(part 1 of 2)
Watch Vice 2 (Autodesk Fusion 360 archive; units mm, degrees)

design "Watch Vice 2" references "WatchCase V3"
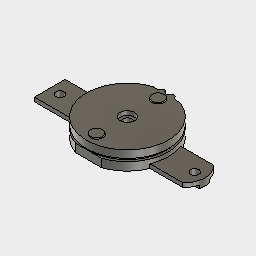
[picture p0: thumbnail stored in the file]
parameter "d90" = 4
parameter "d106" = 4
component_insert "Component Insert"
sketch "Sketch1"
  line L1 (0, 20.2285) -> (0, 20.1)
  line L2 (0, 20.95) -> (0, 20.2285)
  arc A1 centre (0, 0) radius 20.1 clockwise from (19.4682, -5) to (-3.612, 19.7728)
  arc A2 centre (19.1697, -3.3264) radius 1.7 clockwise from (20.869, -3.3751) to (19.4682, -5)
  arc A3 centre (-96.8326, 0) radius 117.75 clockwise from (20.869, 3.3751) to (20.869, -3.3751)
  arc A4 centre (19.1697, 3.3264) radius 1.7 clockwise from (19.4682, 5) to (20.869, 3.3751)
  arc A5 centre (0, 0) radius 20.1 clockwise from (3.612, 19.7728) to (19.4682, 5)
  arc A6 centre (2.1023, 18.9913) radius 1.7 clockwise from (0.8, 20.0841) to (3.612, 19.7728)
  arc A7 centre (0, 0) radius 20.1 clockwise from (-0.8, 20.0841) to (0.8, 20.0841)
  arc A8 centre (-2.1023, 18.9913) radius 1.7 clockwise from (-3.612, 19.7728) to (-0.8, 20.0841)
  arc A9 centre (0, 0) radius 21.6 clockwise from (-17.2241, -13.0342) to (-17.2241, 13.0342)
  arc A10 centre (-18.5, 13.9997) radius 1.6 clockwise from (-16.9962, 14.5462) to (-17.2241, 13.0342)
  arc A11 centre (-15.2104, 15.1952) radius 1.9 clockwise from (-16.9962, 14.5462) to (-14.5633, 16.9815)
  arc A12 centre (-14.0183, 18.4859) radius 1.6 clockwise from (-13.0515, 17.211) to (-14.5633, 16.9815)
  arc A13 centre (0, 0) radius 21.6 clockwise from (-13.0515, 17.211) to (13.0515, 17.211)
  arc A14 centre (14.0183, 18.4859) radius 1.6 clockwise from (14.5633, 16.9815) to (13.0515, 17.211)
  arc A15 centre (15.2104, 15.1952) radius 1.9 clockwise from (14.5633, 16.9815) to (16.9962, 14.5462)
  arc A16 centre (18.5, 13.9997) radius 1.6 clockwise from (17.2241, 13.0342) to (16.9962, 14.5462)
  arc A17 centre (0, 0) radius 21.6 clockwise from (17.2241, 13.0342) to (17.2241, -13.0342)
  arc A18 centre (18.5, -13.9997) radius 1.6 clockwise from (16.9962, -14.5462) to (17.2241, -13.0342)
  arc A19 centre (15.2104, -15.1952) radius 1.9 clockwise from (16.9962, -14.5462) to (14.5633, -16.9815)
  arc A20 centre (14.0183, -18.4859) radius 1.6 clockwise from (13.0515, -17.211) to (14.5633, -16.9815)
  arc A21 centre (0, 0) radius 21.6 clockwise from (13.0515, -17.211) to (-13.0515, -17.211)
  arc A22 centre (-14.0183, -18.4859) radius 1.6 clockwise from (-14.5633, -16.9815) to (-13.0515, -17.211)
  arc A23 centre (-15.2104, -15.1952) radius 1.9 clockwise from (-14.5633, -16.9815) to (-16.9962, -14.5462)
  arc A24 centre (-18.5, -13.9997) radius 1.6 clockwise from (-17.2241, -13.0342) to (-16.9962, -14.5462)
  circle C1 centre (15.2104, 15.1952) radius 0.625
  circle C2 centre (-15.2104, 15.1952) radius 0.625
  circle C3 centre (15.2104, -15.1952) radius 0.625
  circle C4 centre (-15.2104, -15.1952) radius 0.625
  circle C5 centre (5.1662, 20.5772) radius 1.75
  circle C6 centre (-5.1662, 20.5772) radius 1.75
  circle C7 centre (19.7754, 6.7228) radius 1.75
  circle C8 centre (19.7754, -6.7228) radius 1.75
  circle C9 centre (0, 20.1) radius 0.9
  circle C10 centre (0, 20.95) radius 1.75
  arc A25 centre (0, 0) radius 20.1 clockwise from (19.4682, 5) to (19.4682, -5)
  arc A26 centre (0, 0) radius 20.1 clockwise from (0.8, 20.0841) to (3.612, 19.7728)
  arc A27 centre (0, 0) radius 20.1 clockwise from (-3.612, 19.7728) to (-0.8, 20.0841)
  dimension "d6" diameter C8 = 3.5
  dimension "d7" diameter C9 = 1.8
  dimension "d8" diameter C10 = 3.5
extrude "Extrude1" new body sketch "Sketch1" profile of A1 A2 A3 A4 A5 A6 A7 A8 C5 C6 C7 C8 C10 A25 A26 A27 blind 7 bodies "Clamp Bottom"
extrude "Extrude2" cut sketch "Sketch1" profile of A6 A7 A8 C10 no distance stored
work_plane "WorkPlane1" AlongDistance 3
split "Split1" bodies "Clamp Upper"
extrude "Extrude23" add sketch "Sketch1" profile of A1 A5 A7 C5 C6 C7 C8 C10 A26 A27 to an object
extrude "Extrude24" cut sketch "Sketch1" profile of A2 A3 A4 A6 A8 C10 A25 A26 A27 to an object
sketch "Sketch2" plane through (0, 0, 3) normal (0, 0, -1) x axis (1, 0, 0)
  line L1 (0, 15) -> (0, -15)
  circle C1 centre (0, 0) radius 18.9
  circle C2 centre (0, 0) radius 25
  circle C3 centre (0, -15) radius 3
  circle C4 centre (0, 15) radius 3
  circle C5 centre (0, -15) radius 2.9
  circle C6 centre (0, 15) radius 2.9
  circle C7 centre (0, 0) radius 1.7
  point P8 (0, -15)
  point P9 (0, 15)
  dimension "d149" diameter C2 = 50
  dimension "d150" diameter C1 = 37.8
  dimension "d152" diameter C3 = 6
  dimension "d153" distance P8 P9 = 30
  dimension "d154" distance C3 C5 = 0.1
  dimension "d155" diameter C7 = 3.4
extrude "Extrude32" cut sketch "Sketch2" profile of C3 C4 C5 C6 L1 no distance stored
extrude "Extrude25" add sketch "Sketch2" profile of C5 C6 against normal blind 4.5
extrude "Extrude26" cut sketch "Sketch2" profile of L1 C7 no distance stored
extrude "Extrude30" cut sketch "Sketch2" profile of C1 C2 against normal blind 0.4
extrude "Extrude31" cut sketch "Sketch2" profile of C1 C2 along normal blind 1
sketch "Sketch15" plane through (0, 0, 0) normal (0, 1, 0) x axis (1, 0, 0)
  line L1 (1.7, 0) -> (-1.7, 0)
  line L2 (19.4682, 0) -> (20.1, 0)
  line L3 (-20.1, 0) -> (19.4682, 0)
  line L4 (20.1, 3.5) -> (20.1, 0)
  line L5 (-20.1, 3.5) -> (20.1, 3.5)
  line L6 (-20.1, 0) -> (-20.1, 3.5)
  point P8 (20.1, 0)
  point P9 (20.1, 3.5)
  dimension "d161" distance P8 P9 = 3.5
extrude "Extrude28" add sketch "Sketch15" distance 5.05
sketch "Sketch7" plane through (0, 0, 0) normal (0, 0, -1) x axis (1, 0, 0)
  line L1 (38, 7.5) -> (-38, 7.5)
  line L2 (38, -7.5) -> (38, 7.5)
  line L3 (-38, -7.5) -> (38, -7.5)
  line L4 (-38, 7.5) -> (-38, -7.5)
  line L5 (-20, 0) -> (-38, 0)
  line L6 (-34.6144, -7.5) -> (-34.6144, 7.5)
  line L7 (-38, 2.525) -> (-19.9408, 2.525)
  line L8 (-38, -2.525) -> (-19.9408, -2.525)
  line L9 (38, 2.525) -> (19.9408, 2.525)
  line L10 (38, -2.525) -> (19.9408, -2.525)
  line L11 (0, 0) -> (0, 7.5)
  line L12 (0, 0) -> (38, 0)
  line L13 (34.6144, -7.5) -> (34.6144, 7.5)
  line L14 (19.9408, 2.525) -> (-19.9408, 2.525)
  line L15 (-19.9408, -2.525) -> (19.9408, -2.525)
  circle C1 centre (-33, 0) radius 2.025
  arc A1 centre (-28, 0) radius 10 clockwise from (-34.6144, -7.5) to (-34.6144, 7.5)
  arc A2 centre (28, 0) radius 10 clockwise from (34.6144, 7.5) to (34.6144, -7.5)
  circle C2 centre (33, 0) radius 2.025
  arc A3 centre (0, 0) radius 20.1 clockwise from (-19.9408, 2.525) to (19.4682, 5)
  arc A4 centre (0, 0) radius 20.1 clockwise from (19.4682, 5) to (19.9408, 2.525)
  arc A5 centre (0, 0) radius 20.1 clockwise from (19.4682, -5) to (-19.9408, -2.525)
  arc A6 centre (0, 0) radius 20.1 clockwise from (19.9408, -2.525) to (19.4682, -5)
  point P2 (-38, 7.5)
  point P5 (-38, -7.5)
  point P1 (0, 0)
  point P8 (-33, 0)
  point P15 (33, 0)
  dimension "d73" distance P2 P5 = 15
  dimension "d74" distance P1 P8 = 33
  dimension "d76" radius A1 = 10
  dimension "d77" distance L4 P8 = 5
  dimension "d78" diameter C1 = 4.05
  dimension "d138" = 5.2
  dimension "d141" radius A2 = 10
  dimension "d142" diameter C2 = 4.05
  dimension "d143" distance P1 P15 = 33
extrude "Extrude14" add sketch "Sketch7" profile of L1 L3 L4 C1 A2 C2 L7 L8 L9 L10 A3 A4 L14 L15 A5 A6 along normal blind 2
extrude "Extrude15" add sketch "Sketch7" profile of L4 C1 A2 C2 L7 L8 L9 L10 L14 L15 to an object
extrude "Extrude29" cut of existing geometry no distance stored
sketch "Sketch16" plane through (0, 0, 0) normal (0, 1, 0) x axis (1, 0, 0)
  line L1 (20.9174, -7) -> (-20.1, -7)
  line L2 (0, -7) -> (0, 0)
  line L3 (2.05, 0) -> (0, 0)
  line L4 (2.05, -5) -> (2.05, 0)
  line L5 (3.5, -5) -> (2.05, -5)
  line L6 (3.5, -7.8) -> (3.5, -5)
  line L7 (0, -7.8) -> (3.5, -7.8)
  line L8 (0, 0) -> (0, -7.8)
  point P10 (3.5, -7.8)
  point P11 (0, -7.8)
  point P9 (3.5, -5)
  point P5 (0, -7)
  point P6 (0, 0)
  point P7 (2.05, 0)
  dimension "d169" distance P10 P11 = 3.5 (= "( 7 / 2 ) * 1 mm")
  dimension "d170" distance P9 P10 = 2.8
  dimension "d171" distance P5 P9 = 2
  dimension "d172" distance P6 P7 = 2.05 (= "( 4.1 / 2 ) * 1 mm")
revolve "Revolve4" sketch "Sketch16" AlongAngle 360
offset_faces "OffsetFaces4" distance -0.1
delete_face "DeleteFace5"
offset_faces "OffsetFaces5" distance 2
sketch "Sketch17" plane through (0, 0, 7) normal (0, 0, 1) x axis (-1, 0, 0)
  line L1 (-16.7857, 17.8463) -> (-17.8463, 16.7857)
  line L2 (-13.6019, 14.6625) -> (-16.7857, 17.8463)
  line L3 (-14.6625, 13.6019) -> (-13.6019, 14.6625)
  line L4 (-17.8463, 16.7857) -> (-14.6625, 13.6019)
  line L5 (0, 0) -> (-14.1322, 14.1322)
  line L6 (0, 6) -> (0, 0)
  line L7 (-6, 0) -> (0, 0)
  line L8 (13.6019, 14.6625) -> (16.7857, 17.8463)
  line L9 (17.8463, 16.7857) -> (14.6625, 13.6019)
  line L10 (-13.6019, -14.6625) -> (-16.7857, -17.8463)
  line L11 (-17.8463, -16.7857) -> (-14.6625, -13.6019)
  line L12 (13.6019, -14.6625) -> (16.7857, -17.8463)
  line L13 (17.8463, -16.7857) -> (14.6625, -13.6019)
  circle C1 centre (0, 0) radius 3.5
  circle C2 centre (0, 15) radius 3
  circle C3 centre (0, -15) radius 3
  arc A1 centre (0, -20.95) radius 1.85 clockwise from (-1.8093, -20.5643) to (1.8093, -20.5643)
  arc A2 centre (2.1023, -18.9913) radius 1.6 clockwise from (3.5232, -19.7268) to (1.8093, -20.5643)
  arc A3 centre (5.1662, -20.5772) radius 1.85 clockwise from (3.5232, -19.7268) to (6.1713, -19.0241)
  arc A4 centre (0, 0) radius 20 clockwise from (-18.365, 7.92) to (6.1713, -19.0241)
  arc A5 centre (-19.7754, 6.7228) radius 1.85 clockwise from (-18.365, 7.92) to (-19.4506, 4.9016)
  arc A6 centre (-19.1697, 3.3264) radius 1.6 clockwise from (-20.7691, 3.3723) to (-19.4506, 4.9016)
  arc A7 centre (96.8326, 0) radius 117.65 clockwise from (-20.7691, -3.3723) to (-20.7691, 3.3723)
  arc A8 centre (-19.1697, -3.3264) radius 1.6 clockwise from (-19.4506, -4.9016) to (-20.7691, -3.3723)
  arc A9 centre (-19.7754, -6.7228) radius 1.85 clockwise from (-19.4506, -4.9016) to (-18.365, -7.92)
  arc A10 centre (0, 0) radius 20 clockwise from (-6.1713, -19.0241) to (-18.365, -7.92)
  arc A11 centre (-5.1662, -20.5772) radius 1.85 clockwise from (-6.1713, -19.0241) to (-3.5232, -19.7268)
  arc A12 centre (-2.1023, -18.9913) radius 1.6 clockwise from (-1.8093, -20.5643) to (-3.5232, -19.7268)
  arc A13 centre (-18.365, 7.92) radius 4.5 clockwise from (-22.8572, 8.1857) to (-22.4971, 9.702)
  arc A14 centre (0, 0) radius 24.5 clockwise from (-22.4971, 9.702) to (7.5598, -23.3045)
  arc A15 centre (6.1713, -19.0241) radius 4.5 clockwise from (7.5598, -23.3045) to (6.1845, -23.5241)
  arc A16 centre (2.1023, -18.9913) radius 6.1 clockwise from (6.1845, -23.5241) to (0.9855, -24.9882)
  arc A17 centre (1.8093, -20.5643) radius 4.5 clockwise from (0.9855, -24.9882) to (0, -24.6845)
  arc A18 centre (-1.8093, -20.5643) radius 4.5 clockwise from (0, -24.6845) to (-0.9855, -24.9882)
  arc A19 centre (-2.1023, -18.9913) radius 6.1 clockwise from (-0.9855, -24.9882) to (-6.1845, -23.5241)
  arc A20 centre (-6.1713, -19.0241) radius 4.5 clockwise from (-6.1845, -23.5241) to (-7.5598, -23.3045)
  arc A21 centre (0, 0) radius 24.5 clockwise from (-7.5598, -23.3045) to (-22.4971, -9.702)
  arc A22 centre (-18.365, -7.92) radius 4.5 clockwise from (-22.4971, -9.702) to (-22.8572, -8.1857)
  arc A23 centre (-19.1697, -3.3264) radius 6.1 clockwise from (-22.8572, -8.1857) to (-25.2672, -3.5013)
  arc A24 centre (96.8326, 0) radius 122.15 clockwise from (-25.2672, -3.5013) to (-25.2672, 3.5013)
  arc A25 centre (-19.1697, 3.3264) radius 6.1 clockwise from (-25.2672, 3.5013) to (-22.8572, 8.1857)
  arc A26 centre (0, 0) radius 20 clockwise from (-18.365, -7.92) to (-18.365, 7.92)
  point P12 (-18.365, 7.92)
  point P53 (-17.8463, 16.7857)
  point P54 (-16.7857, 17.8463)
  point P58 (0, 0)
  point P59 (0, 6)
  dimension "d177" distance P12 = 4.5
  dimension "d178" distance P53 P54 = 1.5
  dimension "d179" distance P58 P59 = 6
  dimension "d180" angle L5 L6 = 45
extrude "Extrude33" add sketch "Sketch17" profile of A4 A10 A14 A21 L1 L2 L4 L8 L9 L10 L11 L12 L13 against normal blind 1.5
extrude "Extrude36" sketch "Sketch17" profile of A5 A6 A7 A8 A9 A26 to an object
extrude "Extrude37" add sketch "Sketch17" profile of A5 A9 A26 to an object
sketch "Sketch18" plane through (0, 0, -2) normal (0, 0, -1) x axis (1, 0, 0)
  line L1 (34.6144, -7.5) -> (18.5405, -7.5)
  line L2 (-38, -2.525) -> (37.676, -2.525)
  line L3 (-38, -7.5) -> (-38, -2.525)
  line L4 (-18.5405, -7.5) -> (-38, -7.5)
  line L5 (-38, 7.5) -> (-18.5405, 7.5)
  line L6 (-38, 2.525) -> (-38, 7.5)
  line L7 (37.676, 2.525) -> (-38, 2.525)
  line L8 (18.5405, 7.5) -> (34.6144, 7.5)
  line L9 (-38, 2.525) -> (-38, -2.525)
  line L10 (-42, 2.525) -> (-42, -2.525)
  line L11 (-42, 2.525) -> (-42, 11.5)
  line L12 (-42, 11.5) -> (-21.0654, 11.5)
  line L13 (21.0654, 11.5) -> (35.9844, 11.5)
  line L14 (35.9844, -11.5) -> (21.0654, -11.5)
  line L15 (-21.0654, -11.5) -> (-42, -11.5)
  line L16 (-42, -11.5) -> (-42, -2.525)
  line L17 (26.5405, -11.5) -> (28.0405, -11.5)
  line L18 (26.5405, -7.5) -> (26.5405, -11.5)
  line L19 (28.0405, -7.5) -> (26.5405, -7.5)
  line L20 (28.0405, -11.5) -> (28.0405, -7.5)
  line L21 (0, -22.5) -> (0, -1.75)
  line L22 (22.5, 0) -> (1.75, 0)
  line L23 (-26.5405, -7.5) -> (-26.5405, -11.5)
  line L24 (-28.0405, -11.5) -> (-28.0405, -7.5)
  line L25 (28.0405, 11.5) -> (28.0405, 7.5)
  line L26 (26.5405, 7.5) -> (26.5405, 11.5)
  line L27 (-26.5405, 7.5) -> (-26.5405, 11.5)
  line L28 (-28.0405, 11.5) -> (-28.0405, 7.5)
  line L29 (6.245, 19) -> (-6.245, 19)
  line L30 (6.8557, 23) -> (-6.8557, 23)
  line L31 (6.245, -19) -> (-6.245, -19)
  line L32 (6.8557, -23) -> (-6.8557, -23)
  line L33 (-58.9609, 39.0439) -> (-58.9609, -32.8787)
  line L34 (56.2082, 39.0439) -> (-58.9609, 39.0439)
  line L35 (56.2082, -32.8787) -> (56.2082, 39.0439)
  line L36 (-58.9609, -32.8787) -> (56.2082, -32.8787)
  arc A1 centre (0, 0) radius 20 clockwise from (18.5405, -7.5) to (-18.5405, -7.5)
  arc A2 centre (28, 0) radius 10 clockwise from (37.676, -2.525) to (34.6144, -7.5)
  arc A3 centre (0, 0) radius 20 clockwise from (-18.5405, 7.5) to (18.5405, 7.5)
  arc A4 centre (28, 0) radius 10 clockwise from (34.6144, 7.5) to (37.676, 2.525)
  arc A5 centre (28, 0) radius 10 clockwise from (37.676, 2.525) to (37.676, -2.525)
  arc A6 centre (0, 0) radius 24 clockwise from (-21.0654, 11.5) to (21.0654, 11.5)
  arc A7 centre (28, 0) radius 14 clockwise from (35.9844, 11.5) to (41.5464, 3.535)
  arc A8 centre (28, 0) radius 14 clockwise from (41.5464, 3.535) to (41.5464, -3.535)
  arc A9 centre (28, 0) radius 14 clockwise from (41.5464, -3.535) to (35.9844, -11.5)
  arc A10 centre (0, 0) radius 24 clockwise from (21.0654, -11.5) to (-21.0654, -11.5)
  circle C1 centre (-33, 0) radius 2.025
  circle C2 centre (33, 0) radius 2.025
  circle C3 centre (-33, 0) radius 4
  circle C4 centre (33, 0) radius 4
  point P40 (28.0405, -11.5)
  point P41 (26.5405, -11.5)
  point P3 (18.5405, -7.5)
  dimension "d183" = 4
  dimension "d184" distance P40 P41 = 1.5
  dimension "d185" distance P3 L18 = 8
  dimension "d188" distance A3 L29 = 1
  dimension "d189" distance L29 L30 = 4 (= "d183")
  dimension "d194" diameter C3 = 8
extrude "Extrude35" cut sketch "Sketch18" profile of A1 A3 L29 L31 against normal blind 4
mesh "Mesh3"
mesh "Mesh4"
named bodies: "Clamp Bottom", "Clamp Upper"

design "WatchCase V3" references "Watch Vice Fixture CAD"
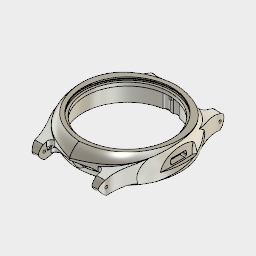
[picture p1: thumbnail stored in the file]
parameter "LugSpacing" = 24
parameter "d280" = 4
sketch "Sketch1"
  line L1 (8, 14) -> (-8, 14)
  line L2 (8, -14) -> (8, 14)
  line L3 (-8, -14) -> (8, -14)
  line L4 (-8, 14) -> (-8, -14)
  line L5 (0, 0) -> (0, 14)
  line L6 (8, 0) -> (0, 0)
  line L7 (0, 14) -> (0, 20.1)
  line L8 (18.5, 5.2) -> (15.5, 5.2)
  line L9 (18.5, -5.2) -> (18.5, 5.2)
  line L10 (15.5, -5.2) -> (18.5, -5.2)
  line L11 (15.5, 5.2) -> (15.5, -5.2)
  line L12 (8, 0) -> (15.5, 0)
  line L13 (19.5, 2.25) -> (18.5, 2.25)
  line L14 (19.5, -2.25) -> (19.5, 2.25)
  line L15 (18.5, -2.25) -> (19.5, -2.25)
  line L16 (19.5, 0.75) -> (18.5, 0.75)
  line L17 (19.5, -0.75) -> (18.5, -0.75)
  line L18 (19.5, 0.75) -> (19.5, -0.75)
  line L19 (18.5, 0) -> (19.5, 0)
  line L20 (-0.8, 20.0841) -> (-0.8, 19.9841)
  line L21 (0.8, 20.0841) -> (0.8, 19.9841)
  circle C1 centre (0, 0) radius 20.1
  circle C2 centre (0, 0) radius 18.85
  circle C3 centre (0, 0) radius 10
  arc A1 centre (0, 19.9841) radius 0.8 clockwise from (0.8, 19.9841) to (-0.8, 19.9841)
  point P4 (-8, 14)
  point P5 (8, 14)
  point P6 (8, -14)
  point P13 (15.5, 5.2)
  point P16 (15.5, -5.2)
  point P14 (18.5, 5.2)
  point P3 (0, 0)
  point P23 (19.5, 0.75)
  point P25 (19.5, -0.75)
  point P29 (0.8, 19.9841)
  point P32 (0.8, 20.0841)
  dimension "d1" diameter C1 = 40.2
  dimension "d3" distance C1 C2 = 1.25
  dimension "d4" diameter C3 = 20
  dimension "d5" distance P4 P5 = 16
  dimension "d6" distance P5 P6 = 28
  dimension "d22" distance P13 P16 = 10.4
  dimension "d23" distance P13 P14 = 3
  dimension "d24" distance P3 L9 = 18.5
  dimension "d25" distance P23 P25 = 1.5
  dimension "d26" distance L13 L16 = 1.5
  dimension "d45" distance P3 = 5.5
  dimension "d108" distance P3 = 1.5
  dimension "d262" distance P3 = 16.5
  dimension "d266" distance P3 = 22
  dimension "d312" radius A1 = 0.8
  dimension "d313" distance P29 P32 = 0.1
  dimension "d170" OffsetX = 0
  dimension "d171" OffsetY = 0
  dimension "d172" OffsetZ = 0
  dimension "d173" AngleZ = 0
  dimension "d194" OffsetX = 0
  dimension "d195" OffsetY = 0
  dimension "d196" OffsetZ = 0
  dimension "d197" AngleZ = 0
extrude "Extrude1" new body sketch "Sketch1" profile of C1 C2 L1 L2 L3 L4 C3 L8 L9 L10 L11 L13 L14 L15 L16 L17 L18 A1 L20 L21 blind 1.6 bodies "WatchBlank"
extrude "Extrude2" add sketch "Sketch1" profile of L1 L2 L3 L4 C3 blind -5.8
extrude "Extrude3" add sketch "Sketch1" profile of C2 L1 L2 L3 L4 C3 blind 3.1
work_plane "WorkPlane1" AlongDistance -14.2
sketch "Sketch2" plane through (-14.2, 0, 0) normal (1, 0, 0) x axis (0, 1, 0)
  line L1 (3.95, -3) -> (3.95, 0)
  line L2 (-3.95, -3) -> (3.95, -3)
  line L3 (-3.95, 0) -> (-3.95, -3)
  line L4 (3.95, 0) -> (-3.95, 0)
  line L5 (0, -3) -> (0, 0)
  line L6 (-20.1, 0) -> (20.1, 0)
  point P2 (3.95, 0)
  point P5 (-3.95, 0)
  point P4 (-3.95, -3)
  dimension "d18" distance P2 P5 = 7.9
  dimension "d19" distance P4 P5 = 3
extrude "Extrude4" add sketch "Sketch2" profile of L1 L2 L3 L4 L6 against normal blind 6.56
extrude "Extrude5" add sketch "Sketch1" profile of C2 L8 L9 L10 L11 blind -2
extrude "Extrude6" add sketch "Sketch1" profile of C2 L9 L14 L16 L17 L18 blind -1.75 second side blind 1.15 (= "1.75 mm - 0.6 mm")
work_plane "WorkPlane2"
sketch "Sketch3" plane through (0, 0, -1.35) normal (0, 0, 1) x axis (1, 0, 0)
  line L1 (0, -22) -> (0, 1)
  line L2 (0, 22) -> (0, 0)
  line L3 (22, 0) -> (0, 0)
  line L4 (0, 27.5) -> (0, 22)
  line L5
  curve K1 (0, 27.5) -> (0, -27.5)
  curve K2 (-6, 28) -> (6, 27)
  curve K3 (7.7672, -26.1119) -> (-7.7672, -28.8881)
  curve K4 (26, 9) -> (26, -5)
  circle C1 centre (0, 0) radius 19
  circle C2 centre (0, 0) radius 22
  circle C3 centre (0, 0) radius 32
  point P6 (0, -22)
  point P10 (0, -27.5)
  point P8 (0, 22)
  point P11 (0, 27.5)
  dimension "d33" diameter C1 = 38
  dimension "d34" distance C1 C2 = 3
  dimension "d44" distance C2 C3 = 10
  dimension "d45" distance P6 P10 = 5.5
  dimension "d46" distance P8 P11 = 5.5
sketch "Sketch8" plane through (0, 0, -1.35) normal (0, 0, 1) x axis (1, 0, 0)
  curve K1 (0, 27.5) -> (0, -27.5)
  line L1 (0, 27.5) -> (0, 22)
  curve K2 (-5.077, 27.7287) -> (5.077, 27.2713)
  curve K3 (7.4837, -26.6298) -> (-7.4837, -28.3702)
  curve K4 (26.5114, 8) -> (26.5114, -6)
sketch "Sketch6" plane through (0, 0, 0) normal (1, 0, 0) x axis (0, 1, 0)
  line L1 (-22, 4.15) -> (-22, -6.85)
  line L2 (-22, -6.85) -> (-27, -6.85)
  line L3 (-35, -6.85) -> (-27, -6.85)
  line L4 (-35, 4.15) -> (-35, -6.85)
  line L5 (-22, 4.15) -> (-35, 4.15)
  line L6 (22, -6.85) -> (22, 4.15)
  line L7 (35, -6.85) -> (22, -6.85)
  line L8 (35, 4.15) -> (35, -6.85)
  line L9 (22, 4.15) -> (35, 4.15)
  arc A1 centre (-17.2456, -4.6475) radius 10 clockwise from (-27, -6.85) to (-22, 4.15)
  arc A2 centre (15.8225, -0.8201) radius 10 clockwise from (24.5, 4.15) to (23.8, -6.85)
  arc A3 centre (3.71, -0.0109) radius 30 clockwise from (-25.5, -6.85) to (-26, 4.15)
  arc A4 centre (-2.256, -13.4898) radius 30 clockwise from (22.01, 4.15) to (27, -6.85)
  point P2 (-22, -6.85)
  point P3 (-22, 4.15)
  point P9 (-35, 4.15)
  point P15 (24.5, 4.15)
  point P16 (23.8, -6.85)
  point P10 (22, 4.15)
  point P21 (22.01, 4.15)
  point P11 (22, -6.85)
  point P22 (27, -6.85)
  point P19 (-25.5, -6.85)
  point P5 (-27, -6.85)
  point P7 (-22, -6.85)
  point P18 (-26, 4.15)
  dimension "d35" distance P2 P3 = 11
  dimension "d36" distance P3 P9 = 13
  dimension "d37" distance L6 P15 = 2.5
  dimension "d38" distance L6 P16 = 1.8
  dimension "d39" radius A2 = 10
  dimension "d47" radius A4 = 30
  dimension "d48" distance P10 P21 = 0.01
  dimension "d49" distance P11 P22 = 5
  dimension "d54" distance P2 P19 = 3.5
  dimension "d55" distance P5 P7 = 5
  dimension "d56" distance P3 P18 = 4
  dimension "d57" radius A3 = 30
  dimension "d68" radius A1 = 10
extrude "Extrude7" new body sketch "Sketch3" profile of C1 C2 C3 distance 11
loft "Loft1" sketch "Sketch6"
loft "Loft2" sketch "Sketch6"
mirror "Mirror1"
offset_faces "OffsetFaces1" distance -0.3
move "Move1"
combine "Combine1"
extrude "Extrude9" cut of existing geometry no distance stored
extrude "Extrude8" cut of existing geometry no distance stored
extrude "Extrude11" cut of existing geometry no distance stored
offset_faces "OffsetFaces3" distance 0.6
extrude "Extrude13" sketch "Sketch1" profile of C1 C2 L8 L9 L10 L13 L14 L15 L18 A1 L20 L21 blind 0 from offset 1.6
sketch "Sketch19" plane through (0, 0, -0.3) normal (0, 0, -1) x axis (1, 0, 0)
  line L1 (0.8, -19.9841) -> (0.8, -20.0841)
  line L2 (-0.8, -20.0841) -> (-0.8, -19.9841)
  line L3 (0, -18) -> (0, -19.1841)
  line L4 (-0.8, -20.0841) -> (-2.1023, -18.9913)
  arc A1 centre (0, -19.9841) radius 0.8 clockwise from (-0.8, -19.9841) to (0.8, -19.9841)
  arc A2 centre (0, 0) radius 20.1 clockwise from (0.8, -20.0841) to (-0.8, -20.0841)
  circle C1 centre (-2.1023, -18.9913) radius 1.7
  circle C2 centre (0, 0) radius 19
  circle C3 centre (2.1023, -18.9913) radius 1.7
  dimension "d322" diameter C1 = 3.4 (= "( 1.7 * 2 ) * 1 mm")
  dimension "d395" angle L3 L4 = 50
extrude "Extrude31" cut sketch "Sketch19" profile of L1 A1 L2 A2 C1 C2 C3 to an object Side2Offset 0
sketch "Sketch9" plane through (0, 0, 0) normal (1, 0, 0) x axis (0, 1, 0)
  line L1 (-9, 2.5959) -> (-9, -2.573)
  line L2 (-9, -4.4041) -> (-25.1866, -7.5504)
  line L3 (-9, -2.573) -> (-9, -4.4041)
  line L4 (-25.5, -4.2) -> (-25.7828, -4.4828)
  line L5 (-22.5, -7.0282) -> (-22.5, -4.2)
  line L6 (-28.5, -1.2) -> (-25.5, -1.2)
  line L7 (-28.5, -4.2) -> (-28.5, -1.2)
  line L8 (-24.3, -4.2) -> (-25.5, -4.2)
  line L9 (-20.2, 0.4492) -> (-20.2, -6.5811)
  line L10 (-21.5832, -6.85) -> (-22.5, -6.85)
  line L11 (-21.5, 0.103) -> (-22.5, -4.2)
  circle C1 centre (-25.7828, -4.4828) radius 0.625
  arc A1 centre (-25.7828, -4.4828) radius 3.125 clockwise from (-25.1866, -7.5504) to (-26.2156, -1.388)
  arc A2 centre (-17.2456, -4.6475) radius 10 clockwise from (-26.2877, -0.3767) to (-22, 4.15)
  arc A3 centre (-40.0649, 97.6484) radius 100 clockwise from (-9, 2.5959) to (-26.2156, -1.388)
  arc A4 centre (-23.4639, -5.5627) radius 5 clockwise from (-28.4301, -6.1435) to (-26.2156, -1.388)
  arc A5 centre (-22.6822, -2.0981) radius 6 clockwise from (-25.1866, -7.5504) to (-28.5947, -3.1193)
  circle C2 centre (-25.5, -4.2) radius 0.625
  circle C3 centre (-25.5, -4.2) radius 3
  arc A6 centre (2.3083, -86.6908) radius 90 clockwise from (-26.7933, -1.5257) to (-9, 2.5959)
  arc A7 centre (-23.4639, -5.5627) radius 5 clockwise from (-26.2156, -1.388) to (-26.02, -1.2654)
  point P1 (0, 0)
  point P9 (-9, 2.5959)
  point P12 (-9, -4.4041)
  point P13 (-28.4301, -6.1435)
  point P15 (-28.5947, -3.1193)
  point P18 (-25.7828, -4.4828)
  point P19 (-25.5, -4.2)
  point P17 (-25.5, -4.2)
  point P20 (-25.5, -4.2)
  point P22 (-22.5, -4.2)
  point P36 (-21.5, 0.103)
  dimension "d71" distance C1 A1 = 2.5
  dimension "d72" diameter C1 = 1.25
  dimension "d74" radius A3 = 100
  dimension "d75" distance P1 P9 = 9
  dimension "d77" angle L2 L3 = 101
  dimension "d78" distance P9 P12 = 7
  dimension "d84" radius A4 = 5
  dimension "d85" distance L2 P13 = 2
  dimension "d86" distance L2 P15 = 5
  dimension "d87" radius A5 = 6
  dimension "d248" diameter C2 = 1.25
  dimension "d249" distance P18 P19 = 0.4
  dimension "d250" distance P1 P17 = 4.2
  dimension "d251" diameter C3 = 6
  dimension "d291" distance P1 P20 = 25.5
  dimension "d293" angle L4 L8 = 45
  dimension "d296" radius A6 = 90
  dimension "d335" distance L5 L9 = 2.3
  dimension "d342" distance P22 P36 = 1
sketch "Sketch15"
  curve K1 (21, -10) -> (14.5, -29)
  curve K2 (16.9276, -20.523) -> (16.0724, -23.477)
  curve K3 (15.7524, -27.1106) -> (13.2476, -30.8894)
  curve K4 (21.5784, -7.8364) -> (20.4216, -12.1636)
  line L1 (12.1, -10) -> (21, -10)
  line L2 (12.1, -29) -> (12.1, -10)
  line L3 (12.1, -29) -> (14.5, -29)
  arc A1 centre (0, 0) radius 20.2 clockwise from (17.5511, -10) to (12.1, -16.175)
  point P1 (0, 0)
  point P3 (16.5, -22)
  point P2 (14.5, -29)
  point P13 (0, 0)
  point P4 (21, -10)
  dimension "d262" distance P1 P3 = 16.5
  dimension "d263" distance P2 P13 = 14.5
  dimension "d264" distance P1 P4 = 21
  dimension "d265" distance P1 P4 = 10
  dimension "d266" distance P1 P3 = 22
  dimension "d267" distance P1 P2 = 29
  dimension "d269" distance P1 L2 = 12.1 (= "( 24.2 / 2 ) * 1 mm")
  dimension "d295" radius A1 = 20.2
extrude "Extrude25" cut sketch "Sketch9" profile of A1 L2 A4 A5 C2 C3 L5 L6 L7 A6 A7 distance 20
extrude "Extrude14" new body sketch "Sketch9" profile of L1 L2 L3 A4 A5 C2 C3 L5 L6 A6 A7 along normal blind 0 and along normal blind 40 bodies "Lug1"
extrude "Extrude26" sketch "Sketch15" profile of K1 L1 L2 L3 blind 10 second side blind 10
work_plane "WorkPlane5" AlongDistance 0.25
mirror "Mirror10"
mirror "Mirror6" bodies "Lug2"
mirror "Mirror8" bodies "Lug3", "Lug4"
extrude "Extrude33" new body sketch "Sketch9" profile of L2 C3 L5 A6 L9 L10 L11 to an object Side2Offset 0
mirror "Mirror12"
chamfer "Chamfer4" distance 2.6
combine "Combine2" bodies "Lug1", "Lug2", "Lug4", "Lug3"
offset_faces "OffsetFaces2" distance 0.6665
fillet "Fillet30" radius 1.6
work_plane "WorkPlane7" AlongDistance 0
sketch "Sketch22" plane through (0, -22.5, 0) normal (0, -1, 0) x axis (1, 0, 0)
  line L1 (-9.6626, -9.5527) -> (-10.2743, -2.5603)
  line L2 (-12.1, -9.5527) -> (-9.6626, -9.5527)
  line L3 (-12.1, -4.5527) -> (-12.1, -9.5527)
  line L4 (-7.2621, -9.1294) -> (-9.6626, -9.5527)
  line L5 (-8.1304, -4.2054) -> (-7.2621, -9.1294)
  line L6 (-12.1, -3.575) -> (-12.1, -4.825)
  line L7 (-10.1, -4.5527) -> (-12.1, -4.2)
  line L8 (10.5, -4.2) -> (-10.5, -4.2)
  arc A1 centre (-10.1, -4.5527) radius 2 clockwise from (-12.1, -4.5527) to (-10.2743, -2.5603)
  arc A2 centre (-10.1, -4.5527) radius 2 clockwise from (-10.2743, -2.5603) to (-8.1304, -4.2054)
  point P4 (-12.1, -9.5527)
  point P5 (-12.1, -4.5527)
  dimension "d360" radius A1 = 2
  dimension "d400" distance P4 P5 = 5
  dimension "d401" angle L5 L8 = 80
  dimension "d411" angle L3 L7 = 80
revolve "Revolve1" sketch "Sketch22" AlongAngle 360
extrude "Extrude36" cut sketch "Sketch22" profile of L1 L2 L3 A1 A2 L4 L5 along normal blind 5
mirror "Mirror14"
work_plane "WorkPlane9"
sketch "Sketch24" plane through (0, 0, 0) normal (0.9096, -0.4154, 0) x axis (0.4154, 0.9096, 0)
  line L1 (-25.1899, -4.2146) -> (-25.1899, -2.2146)
  line L2 (-27.1899, -9.5589) -> (-27.1899, -2.5589)
  line L3 (-22.3908, -9.5589) -> (-27.1899, -9.5589)
  curve K1 (-22.3908, -6.85) -> (-22.6825, -4.3183)
  line L4 (-24.6624, -2.5589) -> (-27.1899, -2.5589)
  line L5 (-22.3908, -9.5589) -> (-22.3908, -6.85)
  arc A1 centre (-24.6624, -4.5527) radius 1.9937 between (-22.6825, -4.3183) and (-24.7348, -2.5603)
  point P3 (-25.1899, -2.2146)
  point P6 (-27.1899, -2.5589)
  point P7 (-27.1899, -9.5589)
  dimension "d404" distance P3 P6 = 2
  dimension "d409" distance P6 P7 = 7
sketch "Sketch25" plane through (0, 0, -6.85) normal (0, 0, -1) x axis (1, 0, 0)
  curve K1 (-22.3111, 9.6073) -> (-11.8816, 21.5439)
  curve K2 (-22.3111, 9.6073) -> (-7.0917, -22.0832)
  line L1
  line L2
  line L3 (10.9929, -22.0832) -> (10.0999, -23)
  line L4
  curve K3 (7.0917, -22.0832) -> (22.3111, 9.6073)
  curve K4 (11.8816, 21.5439) -> (22.3111, 9.6073)
  line L5 (-20.16, -3.95) -> (-19.7081, -3.95)
  line L6 (-20.16, 3.95) -> (-20.16, -3.95)
  line L7 (-19.7081, 3.95) -> (-20.16, 3.95)
  line L8
  line L9 (10.1152, 22.5) -> (0, 0)
  line L10 (-7.6641, 22.5) -> (7.6641, 22.5)
  line L11 (10.0999, -23) -> (-10.0999, -23)
  closed curve K5 centre (9.882, 22.5)
  closed curve K6 centre (-9.882, 22.5)
  arc A1 centre (-2.1023, -18.9913) radius 1.7 clockwise from (-0.8, -20.0841) to (-3.612, -19.7728)
  arc A2 centre (0, 0) radius 20.1 clockwise from (-3.612, -19.7728) to (-19.7081, -3.95)
  arc A3 centre (0, 0) radius 20.1 clockwise from (-19.7081, 3.95) to (3.612, -19.7728)
  arc A4 centre (2.1023, -18.9913) radius 1.7 clockwise from (3.612, -19.7728) to (0.8, -20.0841)
  arc A5 centre (0, 0) radius 20.1 clockwise from (0.8, -20.0841) to (-0.8, -20.0841)
  closed curve K7 centre (10.1152, 22.5)
  closed curve K8 centre (-10.1152, 22.5)
  dimension "d406" angle L8 L9 = 47.479
revolve "Revolve5" sketch "Sketch24" AlongAngle 47.479
delete_face "DeleteFace5"
mirror "Mirror18"
delete_face "DeleteFace8"
fillet "Fillet22" radius 2
fillet "Fillet21" radius 1.2
sketch "Sketch10" plane through (0, 0, -6.85) normal (0, 0, -1) x axis (1, 0, 0)
  curve K1 (-22.3111, 9.6073) -> (-17.5274, -15.6265)
  curve K2 (17.5274, -15.6265) -> (22.3111, 9.6073)
  curve K3 (19.1583, 15.1523) -> (22.3111, 9.6073)
  line L1 (0, 0) -> (-15.2104, 15.1952)
  line L2 (-5, 0) -> (0, 0)
  line L3 (0, 0) -> (-5, 0)
  line L4 (0, 5) -> (0, 0)
  curve K4 (-22.3111, 9.6073) -> (-19.1583, 15.1523)
  curve K5 (19.1583, 15.1523) -> (14.1277, 21.5832)
  curve K6 (-14.1277, 21.5832) -> (-19.1583, 15.1523)
  line L5 (12.1, 21.5832) -> (14.1277, 21.5832)
  line L6 (-14.1277, 21.5832) -> (-12.1, 21.5832)
  curve K7 (10.8585, -21.0162) -> (17.5274, -15.6265)
  curve K8 (-17.5274, -15.6265) -> (-10.8585, -21.0162)
  line L7 (-20.16, -3.95) -> (-19.7081, -3.95)
  line L8 (-20.16, 3.95) -> (-20.16, -3.95)
  line L9 (-19.7081, 3.95) -> (-20.16, 3.95)
  line L10 (-12.1, 21.5832) -> (-12.1, 22.5)
  line L11 (12.1, 22.5) -> (12.1, 21.5832)
  line L12 (-12.1, 21.4183) -> (-12.1, 21.5832)
  line L13 (12.1, 21.4183) -> (12.1, 21.5832)
  line L14 (-12.1, 21.5832) -> (-12.1, 21.4183)
  line L15 (12.1, 21.5832) -> (12.1, 21.4183)
  arc A1 centre (0, 0) radius 20.1 clockwise from (0.8, -20.0841) to (-0.8, -20.0841)
  circle C1 centre (0, 0) radius 21.6
  circle C2 centre (-15.2104, 15.1952) radius 0.625
  arc A2 centre (-14.0183, 18.4859) radius 1.6 clockwise from (-13.0515, 17.211) to (-14.5633, 16.9815)
  arc A3 centre (-15.2104, 15.1952) radius 1.9 clockwise from (-16.9962, 14.5462) to (-14.5633, 16.9815)
  arc A4 centre (-18.5, 13.9997) radius 1.6 clockwise from (-16.9962, 14.5462) to (-17.2241, 13.0342)
  arc A5 centre (14.0183, 18.4859) radius 1.6 clockwise from (14.5633, 16.9815) to (13.0515, 17.211)
  arc A6 centre (15.2104, 15.1952) radius 1.9 clockwise from (14.5633, 16.9815) to (16.9962, 14.5462)
  circle C3 centre (15.2104, 15.1952) radius 0.625
  arc A7 centre (18.5, 13.9997) radius 1.6 clockwise from (17.2241, 13.0342) to (16.9962, 14.5462)
  arc A8 centre (-14.0183, -18.4859) radius 1.6 clockwise from (-14.5633, -16.9815) to (-13.0515, -17.211)
  arc A9 centre (-15.2104, -15.1952) radius 1.9 clockwise from (-14.5633, -16.9815) to (-16.9962, -14.5462)
  arc A10 centre (-18.5, -13.9997) radius 1.6 clockwise from (-17.2241, -13.0342) to (-16.9962, -14.5462)
  circle C4 centre (-15.2104, -15.1952) radius 0.625
  arc A11 centre (15.2104, -15.1952) radius 1.9 clockwise from (16.9962, -14.5462) to (14.5633, -16.9815)
  arc A12 centre (14.0183, -18.4859) radius 1.6 clockwise from (13.0515, -17.211) to (14.5633, -16.9815)
  circle C5 centre (15.2104, -15.1952) radius 0.625
  arc A13 centre (18.5, -13.9997) radius 1.6 clockwise from (16.9962, -14.5462) to (17.2241, -13.0342)
  arc A14 centre (2.1023, -18.9913) radius 1.7 clockwise from (3.612, -19.7728) to (0.8, -20.0841)
  arc A15 centre (-2.1023, -18.9913) radius 1.7 clockwise from (-0.8, -20.0841) to (-3.612, -19.7728)
  circle C6 centre (0, 0) radius 21
  circle C7 centre (0, 0) radius 20.5
  arc A16 centre (0, 0) radius 20.1 clockwise from (-3.612, -19.7728) to (-19.7081, -3.95)
  arc A17 centre (0, 0) radius 20.1 clockwise from (-19.7081, 3.95) to (3.612, -19.7728)
  closed curve K9 centre (-9.882, 22.5)
  closed curve K10 centre (-9.882, -23)
  arc A18 centre (0, -0.5) radius 22.3908 clockwise from (8.6949, -21.1337) to (-8.6949, -21.1337)
  closed curve K11 centre (9.882, -23)
  closed curve K12 centre (9.882, 22.5)
  arc A19 centre (0, 0) radius 22.3908 clockwise from (-8.6949, 20.6337) to (8.6949, 20.6337)
  point P17 (0, 0)
  point P18 (-5, 0)
  point P19 (0, 5)
  point P15 (-15.2104, 15.1952)
  point P16 (0, 0)
  dimension "d108" distance A1 C1 = 1.5
  dimension "d109" diameter C2 = 1.25
  dimension "d110" radius A3 = 1.9
  dimension "d112" radius A2 = 1.6
  dimension "d113" distance P17 P18 = 5
  dimension "d114" distance P17 P19 = 5
  dimension "d120" distance P15 P16 = 21.5
  dimension "d330" = 0.5
  dimension "d331" diameter C6 = 42
extrude "Extrude15" cut sketch "Sketch10" profile of A1 C1 C2 A2 A3 A4 A5 A6 C3 A7 A8 A9 A10 C4 A11 A12 C5 A13 against normal blind 1
extrude "Extrude16" cut sketch "Sketch10" profile of C1 C2 C3 C4 C5 against normal blind 4
sketch "Sketch11" plane through (0, 0, 4.15) normal (0, 0, 1) x axis (-1, 0, 0)
  curve K1 (19.4592, -12.045) -> (0, -22.01)
  curve K2 (0, 22) -> (19.4592, -12.045)
  curve K3 (-19.4592, -12.045) -> (0, 22)
  curve K4 (0, -22.01) -> (-19.4592, -12.045)
  circle C1 centre (0, 0) radius 19
  circle C2 centre (0, 0) radius 20.05
  circle C3 centre (0, 0) radius 20.7
  dimension "d125" diameter C2 = 40.1
  dimension "d423" diameter C3 = 41.4 (= "40 mm + 0.7 * 2 mm")
extrude "Extrude17" cut sketch "Sketch11" profile of C1 C2 against normal blind 1.3
extrude "Extrude37" sketch "Sketch11" profile of C2 C3 blind 0.75 from offset 0.05
extrude "Extrude18" cut of existing geometry no distance stored
work_plane "WorkPlane3"
sketch "Sketch12" plane through (0, 0, -1.75) normal (0, 0, 1) x axis (-1, 0, 0)
  line L1 (-24.1674, 0.75) -> (-20.086, 0.75)
  curve K1 (-24.1674, 0.75) -> (-24.2538, -0.75)
  line L2 (-20.086, -0.75) -> (-24.2538, -0.75)
  line L3 (-22.75, -10) -> (-22.75, 10)
  line L4 (0, 0) -> (-22.75, 0)
  line L5 (-32.75, -10) -> (-22.75, -10)
  line L6 (-32.75, 10) -> (-32.75, -10)
  line L7 (-22.75, 10) -> (-32.75, 10)
  line L8 (-20.8112, 5) -> (-20.8112, -5)
  line L9 (-10.8112, -5) -> (-20.8112, -5)
  line L10 (-10.8112, 5) -> (-10.8112, -5)
  line L11 (-20.8112, 5) -> (-10.8112, 5)
  line L12 (-22.9169, -7.75) -> (-32.75, -7.75)
  line L13 (-22.9169, 7.75) -> (-32.75, 7.75)
  line L14 (-27.8334, -10) -> (-27.8334, -7.75)
  line L15 (-27.8334, 10) -> (-27.8334, 7.75)
  arc A1 centre (0, 0) radius 20.1 clockwise from (-20.086, -0.75) to (-20.086, 0.75)
  arc A2 centre (96.8326, 0) radius 120 clockwise from (-22.75, -10) to (-22.75, 10)
  arc A3 centre (96.8326, 0) radius 117.75 clockwise from (-20.8112, -5) to (-20.8112, 5)
  arc A4 centre (0, 0) radius 20.1 clockwise from (19.7081, -3.95) to (3.612, -19.7728)
  arc A5 centre (0, 0) radius 20.1 clockwise from (-3.612, -19.7728) to (19.7081, 3.95)
  arc A6 centre (0, 0) radius 20.1 clockwise from (-3.612, -19.7728) to (3.612, -19.7728)
  point P10 (-22.75, 0)
  point P11 (0, 0)
  point P7 (-22.75, -10)
  point P8 (-22.75, 10)
  point P12 (-32.75, -10)
  point P14 (-20.8112, -5)
  point P15 (-20.8112, 5)
  point P17 (-10.8112, -5)
  dimension "d129" radius A2 = 120
  dimension "d130" distance P10 P11 = 22.75
  dimension "d131" distance P7 P8 = 20
  dimension "d132" distance P7 P12 = 10
  dimension "d147" distance P14 P15 = 10
  dimension "d148" distance P14 P17 = 10
  dimension "d153" distance A2 A3 = 2.25
  dimension "d232" distance L12 L13 = 15.5 (= "12 mm + 3.5 mm")
extrude "Extrude19" cut sketch "Sketch12" profile of A2 L6 L7 L12 L13 along normal blind 7 and against normal blind 2
fillet "Fillet13" radius 1.6
extrude "Extrude21" cut sketch "Sketch12" profile of A1 L1 L2 A3 L9 L10 L11 blind 2
fillet "Fillet31" radius 1.7
work_plane "WorkPlane4" AlongDistance 23.124
sketch "Sketch13" plane through (23.124, 0, 0) normal (1, 0, 0) x axis (0, 1, 0)
  line L1 (-3.6, -3.05) -> (-3.6, -0.45)
  line L2 (3.6, -3.05) -> (-3.6, -3.05)
  line L3 (3.6, -0.45) -> (3.6, -3.05)
  line L4 (-3.6, -0.45) -> (3.6, -0.45)
  line L5 (0.75, -1.45) -> (-0.75, -1.45)
  line L6 (-0.75, -2.05) -> (-0.75, -1.45)
  line L7 (-0.75, -1.75) -> (-3.6, -1.75)
  line L8 (0.75, -1.45) -> (0.75, -2.05)
  dimension "d138" distance L4 L5 = 1
  dimension "d139" distance L1 L6 = 2.85
  dimension "d140" distance L3 L8 = 2.85 (= "d139")
  dimension "d247" = 6.5
extrude "Extrude20" cut sketch "Sketch13" profile of L1 L2 L3 L4 along normal blind 1 and against normal blind 10
fillet "Fillet14" radius 0.75
delete_face "DeleteFace9"
fillet "Fillet32" radius 0.5
sketch "Sketch26"
  line L1 (-28.6909, 32.7863) -> (28.6626, 32.7863)
  line L2 (-28.6909, -32.2863) -> (-28.6909, 32.7863)
  line L3 (28.6626, -32.2863) -> (-28.6909, -32.2863)
  line L4 (28.6626, 32.7863) -> (28.6626, -32.2863)
  curve K1 (22.3111, -9.6073) -> (24.2921, 5.9411)
  line L5 (24.6626, -7.9065) -> (24.6626, 0.4411)
  curve K2 (-19.5699, 15.0454) -> (-22.3111, -9.6073)
  line L6 (-24.6909, 1.8927) -> (-24.6909, -8.4539)
  point P6 (12.1, 28.7863)
  point P7 (24.2921, 5.9411)
  point P9 (24.6626, 0.4411)
  point P11 (-22.3111, -9.6073)
  point P14 (-24.6909, 1.8927)
  point P15 (12.1, -28.2863)
  dimension "d417" distance L1 P6 = 4
  dimension "d418" distance P7 P9 = 5.5
  dimension "d419" distance L4 L5 = 4
  dimension "d420" distance P11 P14 = 11.5
  dimension "d421" distance L2 L6 = 4
  dimension "d422" distance L3 P15 = 4
component_insert "Component Insert"
position "Position2"
sketch "Sketch27" plane through (0, 0, 0) normal (0, 1, 0) x axis (1, 0, 0)
  line L1 (-5.05, 0) -> (0, 0)
  line L2 (-5.05, -2.58) -> (-5.05, 0)
  line L3 (-9.55, -2.58) -> (-5.05, -2.58)
  line L4 (-9.55, -3.36) -> (-9.55, -2.58)
  line L5 (-8.7, -3.36) -> (-9.55, -3.36)
  line L6 (-8.7, -11.11) -> (-8.7, -3.36)
  line L7 (-3.175, -11.11) -> (-8.7, -11.11)
  line L8 (-3.175, -42.85) -> (-3.175, -11.11)
  line L9 (0, -42.85) -> (-3.175, -42.85)
  line L10 (0, 0) -> (0, -42.85)
  point P2 (0, 0)
  point P3 (-5.05, 0)
  point P4 (-5.05, -2.58)
  point P5 (-9.55, -2.58)
  point P6 (-9.55, -3.36)
  point P7 (-8.7, -3.36)
  point P8 (-8.7, -11.11)
  point P10 (-3.175, -42.85)
  point P11 (0, -42.85)
  point P12 (0, 0)
  dimension "d428" distance P2 P3 = 5.05 (= "( 10.1 / 2 ) * 1 mm")
  dimension "d429" distance P3 P4 = 2.58
  dimension "d430" distance P5 P6 = 0.78
  dimension "d431" distance L4 L10 = 9.55 (= "( 19.1 / 2 ) * 1 mm")
  dimension "d432" distance L6 L10 = 8.7 (= "( 17.4 / 2 ) * 1 mm")
  dimension "d433" distance P7 P8 = 7.75
  dimension "d434" distance P10 P11 = 3.175 (= "( 6.35 / 2 ) * 1 mm")
  dimension "d435" distance P11 P12 = 42.85
mesh "Mesh7"
mesh "Mesh8"
named bodies: "WatchBlank", "WatchCase", "Lug3", "Lug1", "Lug2", "Lug4"

design "Watch Vice Fixture CAD"
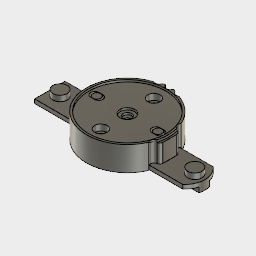
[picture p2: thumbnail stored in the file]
parameter "d90" = 4
parameter "d106" = 4
sketch "Sketch1"
  line L1 (0, 20.2285) -> (0, 20.1)
  line L2 (0, 20.95) -> (0, 20.2285)
  arc A1 centre (0, 0) radius 20.1 clockwise from (19.4682, -5) to (-3.612, 19.7728)
  arc A2 centre (19.1697, -3.3264) radius 1.7 clockwise from (20.869, -3.3751) to (19.4682, -5)
  arc A3 centre (-96.8326, 0) radius 117.75 clockwise from (20.869, 3.3751) to (20.869, -3.3751)
  arc A4 centre (19.1697, 3.3264) radius 1.7 clockwise from (19.4682, 5) to (20.869, 3.3751)
  arc A5 centre (0, 0) radius 20.1 clockwise from (3.612, 19.7728) to (19.4682, 5)
  arc A6 centre (2.1023, 18.9913) radius 1.7 clockwise from (0.8, 20.0841) to (3.612, 19.7728)
  arc A7 centre (0, 0) radius 20.1 clockwise from (-0.8, 20.0841) to (0.8, 20.0841)
  arc A8 centre (-2.1023, 18.9913) radius 1.7 clockwise from (-3.612, 19.7728) to (-0.8, 20.0841)
  arc A9 centre (0, 0) radius 21.6 clockwise from (-17.2241, -13.0342) to (-17.2241, 13.0342)
  arc A10 centre (-18.5, 13.9997) radius 1.6 clockwise from (-16.9962, 14.5462) to (-17.2241, 13.0342)
  arc A11 centre (-15.2104, 15.1952) radius 1.9 clockwise from (-16.9962, 14.5462) to (-14.5633, 16.9815)
  arc A12 centre (-14.0183, 18.4859) radius 1.6 clockwise from (-13.0515, 17.211) to (-14.5633, 16.9815)
  arc A13 centre (0, 0) radius 21.6 clockwise from (-13.0515, 17.211) to (13.0515, 17.211)
  arc A14 centre (14.0183, 18.4859) radius 1.6 clockwise from (14.5633, 16.9815) to (13.0515, 17.211)
  arc A15 centre (15.2104, 15.1952) radius 1.9 clockwise from (14.5633, 16.9815) to (16.9962, 14.5462)
  arc A16 centre (18.5, 13.9997) radius 1.6 clockwise from (17.2241, 13.0342) to (16.9962, 14.5462)
  arc A17 centre (0, 0) radius 21.6 clockwise from (17.2241, 13.0342) to (17.2241, -13.0342)
  arc A18 centre (18.5, -13.9997) radius 1.6 clockwise from (16.9962, -14.5462) to (17.2241, -13.0342)
  arc A19 centre (15.2104, -15.1952) radius 1.9 clockwise from (16.9962, -14.5462) to (14.5633, -16.9815)
  arc A20 centre (14.0183, -18.4859) radius 1.6 clockwise from (13.0515, -17.211) to (14.5633, -16.9815)
  arc A21 centre (0, 0) radius 21.6 clockwise from (13.0515, -17.211) to (-13.0515, -17.211)
  arc A22 centre (-14.0183, -18.4859) radius 1.6 clockwise from (-14.5633, -16.9815) to (-13.0515, -17.211)
  arc A23 centre (-15.2104, -15.1952) radius 1.9 clockwise from (-14.5633, -16.9815) to (-16.9962, -14.5462)
  arc A24 centre (-18.5, -13.9997) radius 1.6 clockwise from (-17.2241, -13.0342) to (-16.9962, -14.5462)
  circle C1 centre (15.2104, 15.1952) radius 0.625
  circle C2 centre (-15.2104, 15.1952) radius 0.625
  circle C3 centre (15.2104, -15.1952) radius 0.625
  circle C4 centre (-15.2104, -15.1952) radius 0.625
  circle C5 centre (5.1662, 20.5772) radius 1.75
  circle C6 centre (-5.1662, 20.5772) radius 1.75
  circle C7 centre (19.7754, 6.7228) radius 1.75
  circle C8 centre (19.7754, -6.7228) radius 1.75
  circle C9 centre (0, 20.1) radius 0.9
  circle C10 centre (0, 20.95) radius 1.75
  arc A25 centre (0, 0) radius 20.1 clockwise from (19.4682, 5) to (19.4682, -5)
  dimension "d6" diameter C8 = 3.5
  dimension "d7" diameter C9 = 1.8
  dimension "d8" diameter C10 = 3.5
extrude "Extrude1" new body sketch "Sketch1" profile of A1 A2 A3 A4 A5 A6 A7 A8 C5 C6 C7 C8 C10 blind 10
extrude "Extrude2" cut sketch "Sketch1" profile of A6 A7 A8 C10 no distance stored
extrude "Extrude3" sketch "Sketch1" profile of A2 A3 A4 A25 blind -1.1
offset_faces "OffsetFaces1" distance -0.1
sketch "Sketch2" plane through (0, 0, 0) normal (1, 0, 0) x axis (0, 1, 0)
  line L1 (-20, 10) -> (19.1, 10)
  line L2 (0, 3) -> (0, 0)
  line L3 (20, 3) -> (-20, 3)
  line L4 (0, 10) -> (0, 3)
  line L5 (-20, 3) -> (-20, 10)
  line L6 (-16, 6) -> (-16, 10)
  line L7 (-14.55, 6) -> (-16, 6)
  line L8 (-14.55, 3) -> (-14.55, 6)
  line L9 (-11.45, 6) -> (-11.45, 3)
  line L10 (-10, 6) -> (-11.45, 6)
  line L11 (-10, 10) -> (-10, 6)
  line L12 (11.45, 6) -> (11.45, 3)
  line L13 (10, 6) -> (11.45, 6)
  line L14 (10, 10) -> (10, 6)
  line L15 (-11.45, 6) -> (-14.55, 6)
  line L16 (-13, 10) -> (-13, 6)
  line L17 (-13, 3) -> (-13, 6)
  line L18 (13, 10) -> (13, 6)
  line L19 (13, 3) -> (13, 6)
  line L20 (-20, 0) -> (19.0241, 0)
  line L21 (-14.25, 0) -> (-14.25, 3)
  line L22 (-13, 0) -> (-13, 3)
  line L23 (-11.75, 0) -> (-11.75, 3)
  line L24 (-11.75, 3) -> (-14.25, 3)
  line L25 (13, 0) -> (13, 3)
  line L26 (11.75, 0) -> (11.75, 3)
  point P10 (-16, 10)
  point P11 (-16, 6)
  point P1 (0, 0)
  dimension "d19" distance P10 P11 = 4
  dimension "d20" distance L8 L9 = 3.1
  dimension "d22" distance L4 L11 = 10
  dimension "d23" distance L6 L11 = 6
  dimension "d24" distance P1 L3 = 3
  dimension "d27" distance L21 L23 = 2.5
  dimension "d28" distance L7 L20 = 6
revolve "Revolve1" sketch "Sketch2" AlongAngle 360
revolve "Revolve2" sketch "Sketch2" AlongAngle 360
work_plane "WorkPlane1" AlongDistance 3
split "Split1" bodies "Clamp Upper"
sketch "Sketch4" plane through (0, 0, 0) normal (0, 1, 0) x axis (1, 0, 0)
  line L1 (-20, 0) -> (20.8174, 0)
  line L2 (20.8174, 4) -> (20.8174, 0)
  line L3 (-20, 4) -> (20.8174, 4)
  line L4 (-20, 0) -> (-20, 4)
  point P4 (20.8174, 0)
  point P5 (20.8174, 4)
  dimension "d41" distance P4 P5 = 4
extrude "Extrude5" add sketch "Sketch4" distance 5.2
delete_face "DeleteFace1"
sketch "Sketch7" plane through (0, 0, 0) normal (0, 0, -1) x axis (1, 0, 0)
  line L1 (20.7887, 2.6) -> (-19.8303, 2.6)
  line L2 (38, 7.5) -> (-38, 7.5)
  line L3 (38, -7.5) -> (38, 7.5)
  line L4 (-38, -7.5) -> (38, -7.5)
  line L5 (-38, 7.5) -> (-38, -7.5)
  line L6 (-19.8303, -2.6) -> (20.7887, -2.6)
  line L7 (-20, 0) -> (-38, 0)
  line L8 (-34.6144, -7.5) -> (-34.6144, 7.5)
  line L9 (0, 7.5) -> (0, 0)
  line L10 (-38, 2.6) -> (-19.8303, 2.6)
  line L11 (-38, -2.6) -> (-19.8303, -2.6)
  line L12 (38, 2.6) -> (20.7887, 2.6)
  line L13 (40.3124, -2.6) -> (20.7887, -2.6)
  arc A1 centre (-96.8326, 0) radius 117.65 clockwise from (20.7691, 3.3723) to (20.7887, 2.6)
  arc A2 centre (19.1697, 3.3264) radius 1.6 clockwise from (19.4506, 4.9016) to (20.7691, 3.3723)
  arc A3 centre (19.7754, 6.7228) radius 1.85 clockwise from (19.4506, 4.9016) to (18.365, 7.92)
  arc A4 centre (0, 0) radius 20 clockwise from (-19.8303, 2.6) to (18.365, 7.92)
  circle C1 centre (0, 13) radius 1.25
  arc A5 centre (0, 0) radius 20 clockwise from (-19.8303, -2.6) to (-19.8303, 2.6)
  circle C2 centre (-33, 0) radius 2.025
  arc A6 centre (-28, 0) radius 10 clockwise from (-34.6144, -7.5) to (-34.6144, 7.5)
  arc A7 centre (28, 0) radius 10 clockwise from (34.6144, 7.5) to (34.6144, -7.5)
  circle C3 centre (33, 0) radius 2.025
  arc A8 centre (5.1662, -20.5772) radius 1.85 clockwise from (3.5232, -19.7268) to (6.1713, -19.0241)
  arc A9 centre (0, 0) radius 20 clockwise from (18.365, -7.92) to (6.1713, -19.0241)
  arc A10 centre (19.7754, -6.7228) radius 1.85 clockwise from (18.365, -7.92) to (19.4506, -4.9016)
  arc A11 centre (19.1697, -3.3264) radius 1.6 clockwise from (20.7691, -3.3723) to (19.4506, -4.9016)
  arc A12 centre (-96.8326, 0) radius 117.65 clockwise from (20.7691, 3.3723) to (20.7691, -3.3723)
  arc A13 centre (19.1697, 3.3264) radius 1.6 clockwise from (19.4506, 4.9016) to (20.7691, 3.3723)
  arc A14 centre (19.7754, 6.7228) radius 1.85 clockwise from (19.4506, 4.9016) to (18.365, 7.92)
  arc A15 centre (0, 0) radius 20 clockwise from (-6.1713, -19.0241) to (18.365, 7.92)
  arc A16 centre (-5.1662, -20.5772) radius 1.85 clockwise from (-6.1713, -19.0241) to (-3.5232, -19.7268)
  arc A17 centre (-2.1023, -18.9913) radius 1.6 clockwise from (-1.8093, -20.5643) to (-3.5232, -19.7268)
  arc A18 centre (0, -20.95) radius 1.85 clockwise from (-1.8093, -20.5643) to (1.8093, -20.5643)
  arc A19 centre (2.1023, -18.9913) radius 1.6 clockwise from (3.5232, -19.7268) to (1.8093, -20.5643)
  circle C4 centre (0, 13) radius 1.55
  circle C5 centre (0, -13) radius 1.55
  point P12 (-38, 7.5)
  point P15 (-38, -7.5)
  point P1 (0, 0)
  point P23 (-33, 0)
  dimension "d73" distance P12 P15 = 15
  dimension "d74" distance P1 P23 = 33
  dimension "d76" radius A6 = 10
  dimension "d77" distance L5 P23 = 5
  dimension "d78" diameter C2 = 4.05
extrude "Extrude14" add sketch "Sketch7" profile of L1 A1 A2 A3 A4 L2 L4 L5 L6 A5 C2 A6 A7 C3 L10 L11 L12 L13 A8 A9 A10 A11 A12 A13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 along normal blind 2
offset_faces "OffsetFaces3" distance 2
extrude "Extrude15" add sketch "Sketch7" profile of L1 L6 A5 C2 A6 A7 C3 L10 L11 L12 L13 A12 A15 along normal blind 4.5
sketch "Sketch3" plane through (0, 0, 0) normal (0, 1, 0) x axis (1, 0, 0)
  line L1 (20, -10) -> (-20, -10)
  line L2 (0, -7) -> (0, 0)
  line L3 (3.6, -8) -> (3.6, -10)
  line L4 (2.1, -8) -> (3.6, -8)
  line L5 (2.1, -7) -> (2.1, -8)
  line L6 (0, -7) -> (2.1, -7)
  line L7 (0, -10) -> (0, -7)
  line L8 (3.6, -10) -> (0, -10)
  line L9 (20.8174, -3) -> (-20, -3)
  line L10 (-22, -7) -> (22, -7)
  line L11 (-22, -1.4022) -> (-22, -7)
  line L12 (22, -1.4022) -> (-22, -1.4022)
  line L13 (22, -7) -> (22, -1.4022)
  point P5 (3.6, -10)
  point P10 (0, -10)
  point P6 (3.6, -8)
  point P7 (2.1, -8)
  point P8 (2.1, -7)
  point P3 (20, -10)
  point P2 (-20, -10)
  dimension "d29" distance L5 L7 = 2.1
  dimension "d30" distance P5 P10 = 3.6
  dimension "d31" distance P5 P6 = 2
  dimension "d32" distance P7 P8 = 1
  dimension "d34" = 1
  dimension "d35" distance P3 L13 = 2
  dimension "d36" distance P2 L11 = 2
revolve "Revolve3" sketch "Sketch3" AlongAngle 360
extrude "Extrude4" cut sketch "Sketch3" profile of L6 L10 L11 L12 L13 distance 10
extrude "Extrude6" new body of existing geometry blind 5.6 bodies "Clamp Jaw 1"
